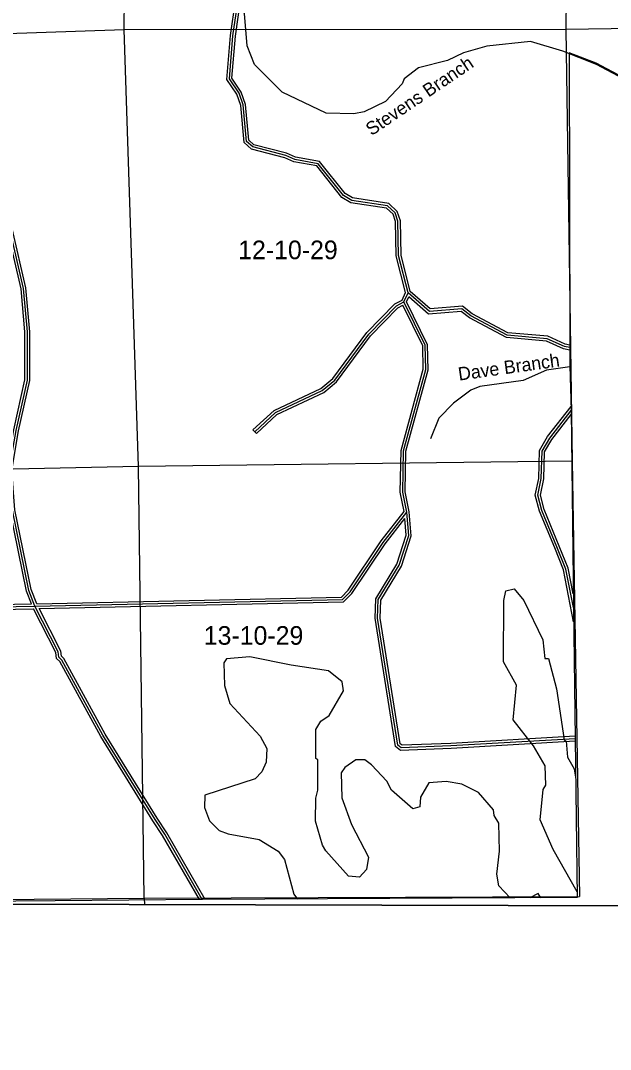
# Model space of a CAD drawing. Extents: x 418523 to 616617, y 1878279 to 2196743.
# Drawn here: x 546469 to 553602, y 1922060 to 1934502 of the extents above; entities that cross this region are included whole.
import ezdxf

# ---------------------------------------------------------------- set-up
doc = ezdxf.new("R2010")
doc.units = 0
for name, color, linetype in [('Level 1', 7, 'Continuous'), ('Level 10', 7, 'Continuous'), ('Level 2', 7, 'Continuous'), ('Level 31', 7, 'Continuous'), ('Level 32', 7, 'Continuous'), ('Level 41', 7, 'Continuous'), ('Level 5', 7, 'Continuous'), ('Level 63', 7, 'Continuous'), ('Level 7', 7, 'Continuous')]:
    doc.layers.add(name, color=color, linetype=linetype)

msp = doc.modelspace()

# ---------------------------------------------------------------- linework, layer by layer
at = {"layer": 'Level 1'}
for p, q in [((553099.543, 1939800.667), (553064.383, 1934399.856)), ((547721.726, 1934392.17), (547776.835, 1939742.916)), ((553064.383, 1934399.856), (558415.125, 1934465.558)), ((542392.857, 1934216.367), (547721.726, 1934392.17)), ((547721.726, 1934392.17), (553064.383, 1934399.856)), ((547894.904, 1929109.019), (547721.726, 1934392.17)), ((553064.383, 1934399.856), (553139.549, 1929172.924)), ((547894.904, 1929109.019), (542626.169, 1928993.131)), ((553139.549, 1929172.924), (547894.904, 1929109.019)), ((547964.075, 1923888.101), (547894.904, 1929109.019)), ((553139.549, 1929172.924), (553226.677, 1923909.95)), ((542659.406, 1923844.323), (547964.075, 1923888.101)), ((547964.075, 1923888.101), (553226.677, 1923909.95)), ((547964.075, 1923888.101), (547966.757, 1923812.126))]:
    msp.add_line(p, q, dxfattribs=at)
at = {"layer": 'Level 10'}
msp.add_lwpolyline([(553755.327, 1933811.649), (553430.318, 1933987.649), (553105.309, 1934113.648), (553111.362, 1930547.563), (553111.366, 1930326.558), (553127.374, 1929786.546), (553154.41, 1927402.49), (553174.434, 1925816.452), (553199.463, 1923897.406), (548667.371, 1923872.347), (546889.334, 1923857.324), (544514.285, 1923836.293), (543165.319, 1923824.675)], dxfattribs=at)
at = {"layer": 'Level 31'}
for p, q in [((551104.938, 1931100.901), (551155.439, 1931209.125)), ((542508.498, 1927339.307), (546643.397, 1927419.913))]:
    msp.add_line(p, q, dxfattribs=at)
for points in [[(551155.439, 1931209.125), (551039.815, 1931659.651), (551032.741, 1932076.412), (550999.353, 1932176.511), (550908.103, 1932260.047), (550474.684, 1932327.832), (550374.787, 1932386.666), (550067.438, 1932770.834), (549784.231, 1932821.832), (549675.736, 1932871.965), (549276.094, 1932973.122), (549201.319, 1933039.886), (549160.667, 1933481.839), (549110.889, 1933623.806), (548994.819, 1933799.058), (549037.93, 1934316.043), (549100.486, 1934747.15)], [(546643.397, 1927419.913), (546568.986, 1927611.777), (546371.388, 1928579.306), (546331.206, 1929063.078), (546415.876, 1929546.116), (546550.791, 1930154.465), (546552.203, 1930737.754), (546503.886, 1931263.37), (546338.921, 1931980.614), (546272.781, 1932172.453), (546181.448, 1932331.277), (546065.491, 1932648.361), (545369.431, 1934217.41), (545311.552, 1934300.86), (545278.651, 1934451.146)], [(553111.421, 1930547.231), (553046.019, 1930561.96), (552837.88, 1930654.544), (552354.492, 1930697.355), (551913.264, 1930932.06), (551805.172, 1931015.641), (551413.067, 1930983.295), (551155.439, 1931209.125)], [(549300.13, 1929530.024), (549550.822, 1929762.761), (550118.337, 1930028.047), (550268.959, 1930152.71), (550678.773, 1930710.102), (551013.306, 1931050.978), (551104.938, 1931100.901)], [(551139.966, 1928558.17), (551090.457, 1928800.137), (551100.139, 1929300.126), (551369.467, 1930283.031), (551362.035, 1930575.062), (551104.938, 1931100.901)], [(553154.123, 1927402.281), (553063.609, 1927869.457), (552956.016, 1928136.312), (552773.941, 1928578.654), (552724.258, 1928762.436), (552766.436, 1928962.324), (552775.627, 1929295.764), (552867.882, 1929453.693), (553127.09, 1929786.435)], [(546643.397, 1927419.913), (550361.761, 1927501.446), (550453.839, 1927592.822), (550855.538, 1928192.058), (551139.966, 1928558.17)], [(553174.489, 1925816.356), (551674.287, 1925730.746), (551073.727, 1925707.356), (551032.2, 1925740.566), (550786.207, 1927275.135), (550795.11, 1927500.208), (551046.327, 1927916.596), (551164.26, 1928274.819), (551139.966, 1928558.17)], [(548667.051, 1923872.036), (548211.821, 1924664.661), (548095.408, 1924839.916), (547464.531, 1925858.527), (546966.807, 1926768.752), (546933.545, 1926801.942), (546925.482, 1926868.877), (546643.397, 1927419.913)]]:
    msp.add_lwpolyline(points, dxfattribs=at)
at = {"layer": 'Level 32'}
for p, q in [((551081.924, 1931122.526), (551123.71, 1931212.073)), ((551138.186, 1931101.201), (551165.723, 1931160.214)), ((549279.718, 1929552.01), (549320.541, 1929508.038)), ((542532.313, 1927369.777), (546599.911, 1927449.072)), ((542543.601, 1927309.983), (546625.237, 1927389.551))]:
    msp.add_line(p, q, dxfattribs=at)
for points in [[(551123.71, 1931212.073), (551009.879, 1931655.612), (551002.823, 1932071.294), (550973.356, 1932159.637), (550894.523, 1932231.806), (550464.392, 1932299.076), (550354.808, 1932363.615), (550051.045, 1932743.303), (549775.134, 1932792.987), (549665.677, 1932843.564), (549261.601, 1932945.844), (549172.526, 1933025.376), (549131.132, 1933475.405), (549083.815, 1933610.354), (548964.057, 1933791.175), (549008.109, 1934319.446), (549069.034, 1934739.316)], [(551182.192, 1931225.568), (551069.751, 1931663.69), (551062.659, 1932081.531), (551025.35, 1932193.386), (550921.683, 1932288.289), (550484.976, 1932356.588), (550394.766, 1932409.716), (550083.832, 1932798.365), (549793.328, 1932850.677), (549685.793, 1932900.366), (549290.586, 1933000.401), (549230.112, 1933054.397), (549190.203, 1933488.273), (549137.964, 1933637.257), (549025.581, 1933806.942), (549067.751, 1934312.639), (549130.167, 1934742.785)], [(546599.911, 1927449.071), (546540.1, 1927603.291), (546341.637, 1928575.048), (546300.988, 1929064.449), (546386.441, 1929551.957), (546520.799, 1930157.787), (546522.199, 1930736.415), (546474.197, 1931258.613), (546310.041, 1931972.339), (546245.35, 1932159.975), (546154.157, 1932318.554), (546037.661, 1932637.114), (545343.161, 1934202.646), (545283.516, 1934288.641), (545257.171, 1934408.976)], [(546663.765, 1927450.367), (546597.874, 1927620.262), (546401.138, 1928583.564), (546361.424, 1929061.708), (546445.31, 1929540.276), (546580.784, 1930151.141), (546582.207, 1930739.094), (546533.576, 1931268.127), (546367.801, 1931988.889), (546300.212, 1932184.932), (546208.74, 1932344), (546093.322, 1932659.608), (545395.703, 1934232.173), (545339.589, 1934313.078), (545317.351, 1934414.653)], [(553111.311, 1930578.007), (553055.503, 1930590.576), (552845.506, 1930683.986), (552363.205, 1930726.701), (551929.601, 1930957.351), (551814.311, 1931046.497), (551423.278, 1931014.24), (551182.192, 1931225.568)], [(549279.718, 1929552.01), (549533.857, 1929787.948), (550102.161, 1930053.602), (550246.98, 1930173.462), (550655.867, 1930729.592), (550995.026, 1931075.183), (551081.924, 1931122.526)], [(549320.541, 1929508.038), (549567.787, 1929737.576), (550134.512, 1930002.491), (550290.938, 1930131.956), (550701.68, 1930690.612), (551031.586, 1931026.773), (551091.76, 1931059.556)], [(551107.809, 1928565.676), (551060.398, 1928797.388), (551070.216, 1929304.446), (551339.364, 1930286.691), (551332.211, 1930567.761), (551091.76, 1931059.555)], [(551169.71, 1928562.471), (551120.517, 1928802.887), (551130.061, 1929295.806), (551399.571, 1930279.371), (551391.86, 1930582.363), (551138.186, 1931101.202)], [(553111.363, 1930516.492), (553036.535, 1930533.343), (552830.255, 1930625.101), (552345.781, 1930668.008), (551896.926, 1930906.769), (551796.033, 1930984.784), (551402.856, 1930952.35), (551165.723, 1931160.214)], [(553156.563, 1927231.966), (553034.705, 1927860.917), (552928.233, 1928124.994), (552745.475, 1928568.991), (552693.415, 1928761.571), (552736.521, 1928965.863), (552745.85, 1929304.266), (552842.986, 1929470.552), (553125.972, 1929833.817)], [(553152.531, 1927568.225), (553092.512, 1927877.998), (552983.801, 1928147.631), (552802.406, 1928588.317), (552755.102, 1928763.3), (552796.351, 1928958.785), (552805.405, 1929287.261), (552892.777, 1929436.833), (553127.917, 1929738.679)], [(546663.765, 1927450.367), (550349.13, 1927531.176), (550430.584, 1927612.011), (550831.203, 1928209.635), (551107.809, 1928565.676)], [(553174.056, 1925846.381), (551672.849, 1925760.713), (551083.732, 1925737.77), (551059.988, 1925756.758), (550816.303, 1927276.933), (550824.781, 1927491.315), (551073.765, 1927903.998), (551194.675, 1928271.267), (551169.71, 1928562.472)], [(546691.918, 1927390.968), (550374.392, 1927471.716), (550477.094, 1927573.634), (550879.872, 1928174.481), (551116.625, 1928479.222)], [(553174.827, 1925786.326), (551675.726, 1925700.778), (551063.722, 1925676.943), (551004.412, 1925724.375), (550756.112, 1927273.336), (550765.437, 1927509.101), (551018.89, 1927929.195), (551133.845, 1928278.371), (551116.625, 1928479.222)], [(548632.446, 1923872.052), (548186.291, 1924648.874), (548070.154, 1924823.714), (547438.598, 1925843.421), (546942.558, 1926750.567), (546905.002, 1926788.043), (546896.338, 1926859.973), (546625.237, 1927389.551)], [(548701.361, 1923872.536), (548237.351, 1924680.448), (548120.661, 1924856.119), (547490.464, 1925873.633), (546991.056, 1926786.937), (546962.088, 1926815.842), (546954.627, 1926877.781), (546691.918, 1927390.969)]]:
    msp.add_lwpolyline(points, dxfattribs=at)
at = {"layer": 'Level 5'}
for points in [[(553026.187, 1934132.137), (552634.767, 1934250.125), (552109.386, 1934193.466), (551825.681, 1934110.991), (551633.659, 1934019.906), (551283.233, 1933929.35), (551107.751, 1933796.524), (551082.541, 1933738.242), (550881.791, 1933522.145), (550622.966, 1933397.918), (550497.825, 1933373.336), (550164.407, 1933382.712), (549631.692, 1933634.541), (549299.32, 1933969.045), (549208.335, 1934194.419), (549176.238, 1934586.357), (548853.111, 1935204.288), (548779.095, 1935521.305), (548745.884, 1935563.085), (548680.466, 1935963.454), (548572.283, 1936022.134)], [(553758.738, 1933796.329), (553434.178, 1933972.439), (553026.187, 1934132.137)], [(553111.759, 1930313.271), (552830.401, 1930273.023), (552546.576, 1930148.896), (552021.156, 1930075.538), (551912.655, 1930034.216), (551703.722, 1929876.479), (551528.071, 1929693.662), (551427.253, 1929443.866)]]:
    msp.add_lwpolyline(points, dxfattribs=at)
at = {"layer": 'Level 63'}
for points in [[(537087.28, 1923840.983), (576804.214, 1923734.416), (576901.847, 1969190.287), (537233.897, 1969297.112), (537087.28, 1923840.983)], [(536941.231, 1878385.707), (576706.958, 1878279.4), (576804.214, 1923734.416), (537087.28, 1923840.983), (536941.231, 1878385.707)]]:
    msp.add_lwpolyline(points, dxfattribs=at)
at = {"layer": 'Level 7'}
for points in [[(553198.551, 1923967.298), (552911.849, 1924478.967), (552754.64, 1924837.913), (552789.156, 1925204.622), (552822.666, 1925254.544), (552815.081, 1925487.96), (552674.115, 1925730.173), (552425.036, 1926047.768), (552468.06, 1926464.458), (552310.582, 1926748.383), (552312.971, 1927490.321), (552338.34, 1927606.964), (552438.471, 1927631.646), (552554.726, 1927489.534), (552786.608, 1927013.606), (552810.892, 1926788.461), (552852.573, 1926788.331), (552951.441, 1926421.203), (553041.171, 1925804.02), (553066.122, 1925787.28), (553082.176, 1925595.476), (553165.08, 1925453.503), (553180.488, 1925352.301)], [(552389.156, 1923892.926), (552251.881, 1924039.228), (552227.329, 1924181.041), (552261.556, 1924456.018), (552254.331, 1924797.836), (552196.268, 1924889.737), (552188.126, 1924956.459), (552005.41, 1925165.451), (551805.634, 1925266.111), (551614.03, 1925300.08), (551405.556, 1925284.096), (551304.966, 1925109.351), (551296.267, 1924992.648), (551212.806, 1924967.936), (550955.097, 1925193.828), (550897.105, 1925302.401), (550714.358, 1925503.062), (550631.156, 1925561.673), (550522.783, 1925562.001), (550389.111, 1925470.758), (550347.231, 1925404.206), (550354.586, 1925104.058), (550470.254, 1924778.552), (550677.424, 1924386.086), (550651.926, 1924236.101), (550568.266, 1924144.688), (550434.912, 1924153.457), (550160.792, 1924462.781), (550119.341, 1924529.601), (550036.894, 1924821.638), (550037.78, 1925096.734), (550063.109, 1925196.707), (550064.283, 1925563.476), (550039.342, 1925580.246), (550040.457, 1925930.374), (550099.137, 1926030.207), (550199.398, 1926096.58), (550375.407, 1926396.13), (550359.096, 1926504.571), (550192.8, 1926638.473), (549742.86, 1926706.598), (549242.977, 1926808.235), (548959.472, 1926784.151), (548925.972, 1926734.259), (548933.426, 1926459.122), (548999.431, 1926242.148), (549364.955, 1925849.163), (549447.829, 1925698.851), (549438.961, 1925532.156), (549388.591, 1925415.613), (549304.931, 1925332.511), (548695.761, 1925134.398), (548695.264, 1924984.344), (548753.127, 1924825.751), (548869.451, 1924708.69), (548977.695, 1924666.641), (549352.593, 1924598.743), (549585.561, 1924456.273), (549660.293, 1924356.011), (549775.662, 1923938.803), (549816.697, 1923878.702)], [(552760.539, 1923894.981), (552726.753, 1923946.021), (552628.949, 1923894.253)]]:
    msp.add_lwpolyline(points, dxfattribs=at)

# ---------------------------------------------------------------- texts
at = {"layer": 'Level 2'}
for s, p in [('12-10-29', (549100.249, 1931616.371)), ('13-10-29', (548684.193, 1926954.032))]:
    msp.add_text(s, height=225, dxfattribs=at).set_placement(p)
at = {"layer": 'Level 41'}
for s, rotation, p in [('Stevens Branch', 34.0905028, (550712.866, 1933102.695)), ('Dave Branch', 7.9956583, (551771.975, 1930147.364))]:
    msp.add_text(s, height=160, rotation=rotation, dxfattribs=at).set_placement(p)

doc.saveas('drawing.dxf')
